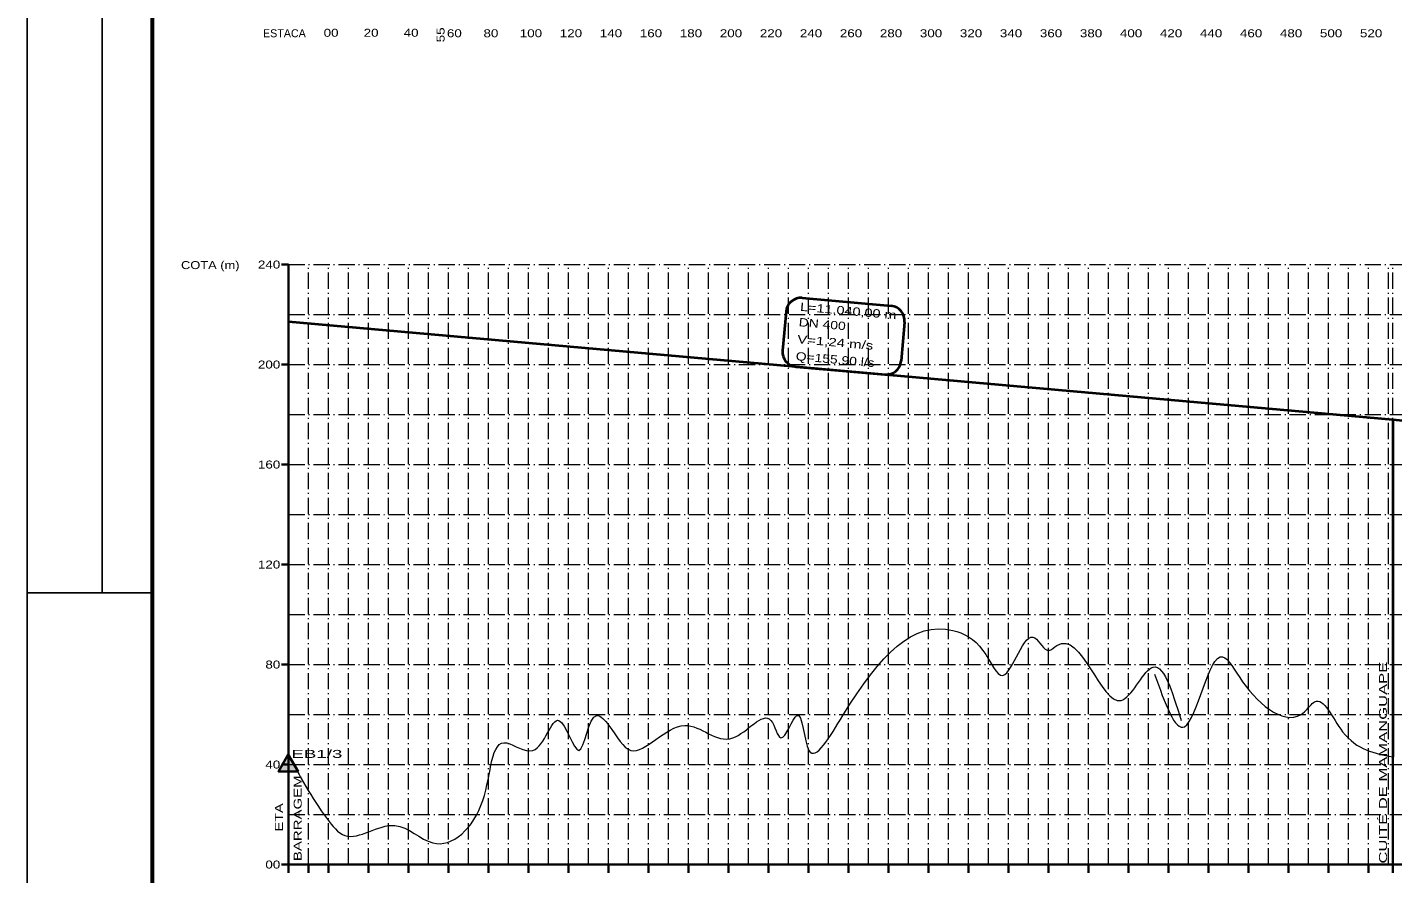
# Model space of a CAD drawing. Extents: x 0 to 1772, y 0 to 1188.
# Drawn here: x 0 to 546, y 482 to 820 of the extents above; entities that cross this region are included whole.
import ezdxf
from ezdxf.enums import TextEntityAlignment as Align

# ---------------------------------------------------------------- set-up
doc = ezdxf.new("R2010")
doc.units = 0
doc.header["$LTSCALE"] = 1.3
doc.linetypes.add('DOT_DASHED', pattern=[7.7, 5, -1.2, 0.3, -1.2])
for name, color, linetype, lineweight in [('1', 7, 'DOT_DASHED', 13), ('24', 7, 'Continuous', 35), ('56', 7, 'Continuous', 13), ('62', 7, 'Continuous', 13), ('63', 7, 'Continuous', 25), ('9', 7, 'Continuous', 40)]:
    doc.layers.add(name, color=color, linetype=linetype, lineweight=lineweight)

msp = doc.modelspace()

# ---------------------------------------------------------------- hatches: boundary and pattern name
at = {"layer": '62'}
msp.add_hatch(color=256, dxfattribs=at).paths.add_polyline_path([(104.18, 529.211), (108.126, 522.473), (100.317, 522.424)])

# ---------------------------------------------------------------- linework, layer by layer
at = {"layer": '1'}
for p, q in [((104.257, 725.251), (913.857, 725.251)), ((112.257, 485.251), (112.257, 725.251)), ((120.257, 485.251), (120.257, 725.251)), ((128.257, 485.251), (128.257, 725.251)), ((136.257, 485.251), (136.257, 725.251)), ((144.257, 485.251), (144.257, 725.251)), ((152.257, 485.251), (152.257, 725.251)), ((160.257, 485.251), (160.257, 725.251)), ((168.257, 485.251), (168.257, 725.251)), ((176.257, 485.251), (176.257, 725.251)), ((184.257, 485.251), (184.257, 725.251)), ((192.257, 485.251), (192.257, 725.251)), ((200.257, 485.251), (200.257, 725.251)), ((208.257, 485.251), (208.257, 725.251)), ((216.257, 485.251), (216.257, 725.251)), ((224.257, 485.251), (224.257, 725.251)), ((232.257, 485.251), (232.257, 725.251)), ((240.257, 485.251), (240.257, 725.251)), ((248.257, 485.251), (248.257, 725.251)), ((256.257, 485.251), (256.257, 725.251)), ((264.257, 485.251), (264.257, 725.251)), ((272.257, 485.251), (272.257, 725.251)), ((280.257, 485.251), (280.257, 725.251)), ((288.257, 485.251), (288.257, 725.251)), ((296.257, 485.251), (296.257, 725.251)), ((304.257, 485.251), (304.257, 725.251)), ((312.257, 485.251), (312.257, 725.251)), ((320.257, 485.251), (320.257, 725.251)), ((328.257, 485.251), (328.257, 725.251)), ((336.257, 485.251), (336.257, 725.251)), ((344.257, 485.251), (344.257, 725.251)), ((352.257, 485.251), (352.257, 725.251)), ((360.257, 485.251), (360.257, 725.251)), ((368.257, 485.251), (368.257, 725.251)), ((376.257, 485.251), (376.257, 725.251)), ((384.257, 485.251), (384.257, 725.251)), ((392.257, 485.251), (392.257, 725.251)), ((400.257, 485.251), (400.257, 725.251)), ((408.257, 485.251), (408.257, 725.251)), ((416.257, 485.251), (416.257, 725.251)), ((424.257, 485.251), (424.257, 725.251)), ((432.257, 485.251), (432.257, 725.251)), ((440.257, 485.251), (440.257, 725.251)), ((448.257, 485.251), (448.257, 725.251)), ((456.257, 485.251), (456.257, 725.251)), ((464.257, 485.251), (464.257, 725.251)), ((472.257, 485.251), (472.257, 725.251)), ((480.257, 485.251), (480.257, 725.251)), ((488.257, 485.251), (488.257, 725.251)), ((496.257, 485.251), (496.257, 725.251)), ((504.257, 485.251), (504.257, 725.251)), ((512.257, 485.251), (512.257, 725.251)), ((520.257, 485.251), (520.257, 725.251)), ((528.257, 485.251), (528.257, 725.251)), ((536.257, 485.251), (536.257, 725.251)), ((544.257, 485.251), (544.257, 725.251)), ((545.857, 485.251), (545.857, 725.251)), ((545.857, 485.251), (545.857, 725.251)), ((104.257, 705.251), (913.857, 705.251)), ((104.257, 685.251), (913.857, 685.251)), ((104.257, 665.251), (913.857, 665.251)), ((104.257, 645.251), (913.857, 645.251)), ((104.257, 625.251), (913.857, 625.251)), ((104.257, 605.251), (913.857, 605.251)), ((104.257, 585.251), (913.857, 585.251)), ((104.257, 565.251), (913.857, 565.251)), ((104.257, 545.251), (913.857, 545.251)), ((104.257, 525.251), (544.257, 525.251)), ((104.257, 525.251), (913.857, 525.251)), ((104.257, 505.251), (544.257, 505.251)), ((104.257, 505.251), (913.857, 505.251))]:
    msp.add_line(p, q, dxfattribs=at)
at = {"layer": '56'}
for points in [[(104.18, 529.211), (119.714, 503.488), (126.819, 496.856), (146.819, 500.856), (162.019, 493.856), (182.019, 510.856), (191.619, 533.856), (202.019, 530.856), (212.419, 542.856), (220.419, 530.856), (227.619, 544.856), (232.419, 540.856), (241.219, 530.856), (262.819, 540.856), (282.019, 535.856), (297.219, 542.856), (301.219, 535.856), (307.619, 544.856), (312.419, 530.856), (326.019, 544.856), (370.019, 578.856), (382.019, 570.856), (390.019, 560.856), (402.819, 575.856), (408.419, 570.856), (411.619, 572.856), (437.219, 550.856), (449.219, 563.856), (461.219, 542.856)], [(450.659, 561.336), (462.659, 540.336), (477.859, 568.336), (485.859, 558.336), (510.659, 546.336), (514.659, 550.336), (525.859, 538.336), (545.859, 528.336)]]:
    msp.add_spline(points, degree=3, dxfattribs=at)
at = {"layer": '62', "lineweight": 35}
for p, q in [((104.257, 725.251), (101.526, 725.251)), ((104.089, 725.251), (104.257, 725.251)), ((104.257, 485.251), (104.257, 725.251)), ((104.089, 715.251), (104.257, 715.251)), ((104.089, 705.251), (104.257, 705.251)), ((104.089, 695.251), (104.257, 695.251)), ((104.257, 685.251), (101.526, 685.251)), ((104.089, 685.251), (104.257, 685.251)), ((104.089, 675.251), (104.257, 675.251)), ((104.089, 665.251), (104.257, 665.251)), ((104.089, 655.251), (104.257, 655.251)), ((104.257, 645.251), (101.526, 645.251)), ((104.089, 645.251), (104.257, 645.251)), ((104.089, 635.251), (104.257, 635.251)), ((104.089, 625.251), (104.257, 625.251)), ((104.089, 615.251), (104.257, 615.251)), ((104.257, 605.251), (101.526, 605.251)), ((104.089, 605.251), (104.257, 605.251)), ((104.089, 595.251), (104.257, 595.251)), ((104.089, 585.251), (104.257, 585.251)), ((104.089, 575.251), (104.257, 575.251)), ((104.257, 565.251), (101.526, 565.251)), ((104.089, 565.251), (104.257, 565.251)), ((104.089, 555.251), (104.257, 555.251)), ((104.089, 545.251), (104.257, 545.251)), ((104.089, 535.251), (104.257, 535.251)), ((104.257, 525.251), (101.526, 525.251)), ((104.089, 525.251), (104.257, 525.251)), ((545.859, 528.336), (545.859, 485.251)), ((104.089, 515.251), (104.257, 515.251)), ((104.089, 505.251), (104.257, 505.251)), ((104.089, 495.251), (104.257, 495.251)), ((104.257, 485.251), (101.526, 485.251)), ((104.257, 485.251), (545.857, 485.251)), ((104.257, 485.251), (104.257, 481.901)), ((112.257, 485.251), (112.257, 481.901)), ((120.257, 485.251), (120.257, 481.901)), ((136.257, 485.251), (136.257, 481.901)), ((152.257, 485.251), (152.257, 481.901)), ((168.257, 485.251), (168.257, 481.901)), ((184.257, 485.251), (184.257, 481.901)), ((200.257, 485.251), (200.257, 481.901)), ((216.257, 485.251), (216.257, 481.901)), ((232.257, 485.251), (232.257, 481.901)), ((248.257, 485.251), (248.257, 481.901)), ((264.257, 485.251), (264.257, 481.901)), ((280.257, 485.251), (280.257, 481.901)), ((296.257, 485.251), (296.257, 481.901)), ((312.257, 485.251), (312.257, 481.901)), ((328.257, 485.251), (328.257, 481.901)), ((344.257, 485.251), (344.257, 481.901)), ((360.257, 485.251), (360.257, 481.901)), ((376.257, 485.251), (376.257, 481.901)), ((392.257, 485.251), (392.257, 481.901)), ((408.257, 485.251), (408.257, 481.901)), ((424.257, 485.251), (424.257, 481.901)), ((440.257, 485.251), (440.257, 481.901)), ((456.257, 485.251), (456.257, 481.901)), ((472.257, 485.251), (472.257, 481.901)), ((488.257, 485.251), (488.257, 481.901)), ((504.257, 485.251), (504.257, 481.901)), ((520.257, 485.251), (520.257, 481.901)), ((536.257, 485.251), (536.257, 481.901)), ((913.857, 485.251), (545.857, 485.251)), ((545.859, 485.251), (545.859, 481.901))]:
    msp.add_line(p, q, dxfattribs=at)
at = {"layer": '62'}
for p, q in [((104.089, 723.251), (104.257, 723.251)), ((104.089, 721.251), (104.257, 721.251)), ((104.089, 719.251), (104.257, 719.251)), ((104.089, 717.251), (104.257, 717.251)), ((104.089, 713.251), (104.257, 713.251)), ((104.089, 711.251), (104.257, 711.251)), ((104.089, 709.251), (104.257, 709.251)), ((104.089, 707.251), (104.257, 707.251)), ((104.089, 703.251), (104.257, 703.251)), ((104.089, 701.251), (104.257, 701.251)), ((104.089, 699.251), (104.257, 699.251)), ((104.089, 697.251), (104.257, 697.251)), ((104.089, 693.251), (104.257, 693.251)), ((104.089, 691.251), (104.257, 691.251)), ((104.089, 689.251), (104.257, 689.251)), ((104.089, 687.251), (104.257, 687.251)), ((104.089, 683.251), (104.257, 683.251)), ((104.089, 681.251), (104.257, 681.251)), ((104.089, 679.251), (104.257, 679.251)), ((104.089, 677.251), (104.257, 677.251)), ((104.089, 673.251), (104.257, 673.251)), ((104.089, 671.251), (104.257, 671.251)), ((104.089, 669.251), (104.257, 669.251)), ((104.089, 667.251), (104.257, 667.251)), ((104.089, 663.251), (104.257, 663.251)), ((104.089, 661.251), (104.257, 661.251)), ((104.089, 659.251), (104.257, 659.251)), ((104.089, 657.251), (104.257, 657.251)), ((104.089, 653.251), (104.257, 653.251)), ((104.089, 651.251), (104.257, 651.251)), ((104.089, 649.251), (104.257, 649.251)), ((104.089, 647.251), (104.257, 647.251)), ((104.089, 643.251), (104.257, 643.251)), ((104.089, 641.251), (104.257, 641.251)), ((104.089, 639.251), (104.257, 639.251)), ((104.089, 637.251), (104.257, 637.251)), ((104.089, 633.251), (104.257, 633.251)), ((104.089, 631.251), (104.257, 631.251)), ((104.089, 629.251), (104.257, 629.251)), ((104.089, 627.251), (104.257, 627.251)), ((104.089, 623.251), (104.257, 623.251)), ((104.089, 621.251), (104.257, 621.251)), ((104.089, 619.251), (104.257, 619.251)), ((104.089, 617.251), (104.257, 617.251)), ((104.089, 613.251), (104.257, 613.251)), ((104.089, 611.251), (104.257, 611.251)), ((104.089, 609.251), (104.257, 609.251)), ((104.089, 607.251), (104.257, 607.251)), ((104.089, 603.251), (104.257, 603.251)), ((104.089, 601.251), (104.257, 601.251)), ((104.089, 599.251), (104.257, 599.251)), ((104.089, 597.251), (104.257, 597.251)), ((104.089, 593.251), (104.257, 593.251)), ((104.089, 591.251), (104.257, 591.251)), ((104.089, 589.251), (104.257, 589.251)), ((104.089, 587.251), (104.257, 587.251)), ((104.089, 583.251), (104.257, 583.251)), ((104.089, 581.251), (104.257, 581.251)), ((104.089, 579.251), (104.257, 579.251)), ((104.089, 577.251), (104.257, 577.251)), ((104.089, 573.251), (104.257, 573.251)), ((104.089, 571.251), (104.257, 571.251)), ((104.089, 569.251), (104.257, 569.251)), ((104.089, 567.251), (104.257, 567.251)), ((104.089, 563.251), (104.257, 563.251)), ((104.089, 561.251), (104.257, 561.251)), ((104.089, 559.251), (104.257, 559.251)), ((104.089, 557.251), (104.257, 557.251)), ((104.089, 553.251), (104.257, 553.251)), ((104.089, 551.251), (104.257, 551.251)), ((104.089, 549.251), (104.257, 549.251)), ((104.089, 547.251), (104.257, 547.251)), ((104.089, 543.251), (104.257, 543.251)), ((104.089, 541.251), (104.257, 541.251)), ((104.089, 539.251), (104.257, 539.251)), ((104.089, 537.251), (104.257, 537.251)), ((104.089, 533.251), (104.257, 533.251)), ((104.089, 531.251), (104.257, 531.251)), ((104.089, 529.251), (104.257, 529.251)), ((104.089, 527.251), (104.257, 527.251)), ((104.089, 523.251), (104.257, 523.251)), ((104.089, 521.251), (104.257, 521.251)), ((104.089, 519.251), (104.257, 519.251)), ((104.089, 517.251), (104.257, 517.251)), ((104.089, 513.251), (104.257, 513.251)), ((104.089, 511.251), (104.257, 511.251)), ((104.089, 509.251), (104.257, 509.251)), ((104.089, 507.251), (104.257, 507.251)), ((104.089, 503.251), (104.257, 503.251)), ((104.089, 501.251), (104.257, 501.251)), ((104.089, 499.251), (104.257, 499.251)), ((104.089, 497.251), (104.257, 497.251)), ((104.089, 493.251), (104.257, 493.251)), ((104.089, 491.251), (104.257, 491.251)), ((104.089, 489.251), (104.257, 489.251)), ((104.089, 487.251), (104.257, 487.251))]:
    msp.add_line(p, q, dxfattribs=at)
at = {"layer": '62', "lineweight": 35}
msp.add_lwpolyline([(104.18, 529.211), (108.126, 522.473), (100.317, 522.424)], close=True, dxfattribs=at)
at = {"layer": '63'}
for p, q in [((-0.167, -0.127), (-0.167, 1187.873)), ((29.833, 593.873), (29.833, 1187.873)), ((-0.167, 593.873), (49.833, 593.873))]:
    msp.add_line(p, q, dxfattribs=at)
at = {"layer": '63', "lineweight": 60}
msp.add_lwpolyline([(49.833, 1167.873), (1751.833, 1167.873), (1751.833, 19.873), (49.833, 19.873)], close=True, dxfattribs=at)
at = {"layer": '9'}
for p, q in [((309.751, 711.849), (345.246, 708.698)), ((303.244, 706.403), (301.864, 690.853)), ((350.692, 702.191), (349.312, 686.642)), ((307.31, 684.346), (342.805, 681.196)), ((545.859, 663.174), (545.859, 528.336))]:
    msp.add_line(p, q, dxfattribs=at)
msp.add_lwpolyline([(104.257, 702.369), (545.857, 663.174), (913.857, 626.933)], dxfattribs=at)
for centre, start, end in [((309.221, 705.872), 84.92792, 174.92792), ((344.715, 702.722), 354.92792, 84.92792), ((307.841, 690.323), 174.92792, 264.92792), ((343.335, 687.173), 264.92792, 354.92792)]:
    msp.add_arc(centre, 6, start, end, dxfattribs=at)

# ---------------------------------------------------------------- texts
at = {"layer": '24'}
msp.add_text('ESTACA', height=3.2, dxfattribs=at).set_placement((102.65, 816.125), align=Align.CENTER)
at = {"layer": '24', "width": 1.25}
for s, p in [('00', (121.315, 816.322)), ('20', (137.315, 816.322)), ('40', (153.315, 816.322)), ('60', (170.612, 816.125)), ('80', (185.24, 816.125)), ('100', (201.24, 816.125)), ('120', (217.24, 816.125)), ('140', (233.24, 816.125)), ('160', (249.24, 816.125)), ('180', (265.24, 816.125)), ('200', (281.24, 816.125)), ('220', (297.24, 816.125)), ('240', (313.24, 816.125)), ('260', (329.24, 816.125)), ('280', (345.24, 816.125)), ('300', (361.24, 816.125)), ('320', (377.24, 816.125)), ('340', (393.24, 816.125)), ('360', (409.24, 816.125)), ('380', (425.24, 816.125)), ('400', (441.24, 816.125)), ('420', (457.24, 816.125)), ('440', (473.24, 816.125)), ('460', (489.24, 816.125)), ('480', (505.24, 816.125)), ('500', (521.24, 816.125)), ('520', (537.24, 816.125))]:
    msp.add_text(s, height=3.2, dxfattribs=at).set_placement(p, align=Align.CENTER)
msp.add_text('55', height=3.2, rotation=90, dxfattribs=at).set_placement((166.711, 817.085), align=Align.CENTER)
at = {"layer": '24'}
for s, width, p in [('COTA (m)', 1.2, (84.696, 723.396)), ('240', 1.25, (100.989, 723.612)), ('200', 1.25, (100.989, 683.612)), ('160', 1.25, (100.989, 643.612)), ('120', 1.25, (100.989, 603.612)), ('80', 1.25, (100.989, 563.612)), ('40', 1.25, (100.989, 523.612)), ('00', 1.25, (100.989, 483.612))]:
    msp.add_text(s, height=3.2, dxfattribs=dict(at, width=width)).set_placement(p, align=Align.RIGHT)
for s, width, p in [('CUITÉ DE MAMANGUAPE', 1.55, (543.608, 485.615)), ('BARRAGEM', 1.4, (109.562, 486.596)), ('ETA', 1.35, (102.057, 498.452))]:
    msp.add_text(s, height=3.2, rotation=90, dxfattribs=dict(at, width=width)).set_placement(p)
at = {"layer": '24', "width": 1.75}
msp.add_text('EB1/3', height=3.2, dxfattribs=at).set_placement((105.435, 527.867))
at = {"layer": '9'}
for s, width, p in [('L=11.040,00 m', 1.3, (308.78, 706.736)), ('DN 400', 1.25, (308.234, 700.58)), ('V=1,24 m/s', 1.35, (307.63, 693.784)), ('Q=155,90 l/s', 1.25, (307.027, 686.987))]:
    msp.add_text(s, height=3.319, rotation=354.928, dxfattribs=dict(at, width=width)).set_placement(p)

doc.saveas('drawing.dxf')
